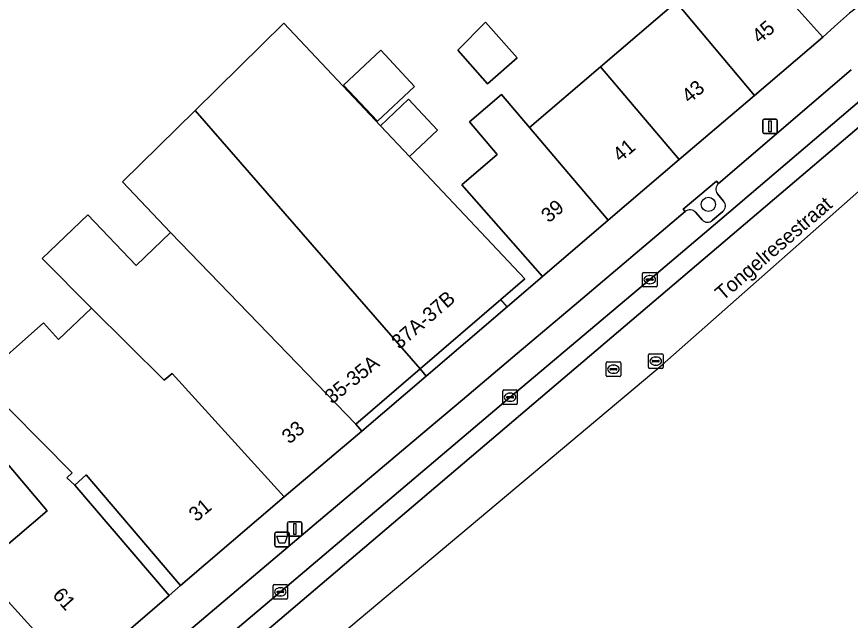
# Model space of a CAD drawing. Extents: x 161772 to 163126, y 383092 to 383917.
# Drawn here: x 162327.9 to 162385.3, y 383254.5 to 383296 of the extents above; entities that cross this region are included whole.
import ezdxf

# ---------------------------------------------------------------- set-up
doc = ezdxf.new("R2010")
doc.units = 0
for name, color, linetype in [('IMGEO_Afvalbak', 7, 'Continuous'), ('IMGEO_Boom', 7, 'Continuous'), ('IMGEO_Erf', 7, 'Continuous'), ('IMGEO_Kolk', 7, 'Continuous'), ('IMGEO_Lichtmast', 7, 'Continuous'), ('IMGEO_Openbare_ruimte_label', 7, 'Continuous'), ('IMGEO_Pand', 7, 'Continuous'), ('IMGEO_Pand_nummerreeks', 7, 'Continuous'), ('IMGEO_Pand_overbouw', 7, 'Continuous'), ('IMGEO_Parkeervlak_open', 7, 'Continuous'), ('IMGEO_Rijbaan_lokaal_gesloten', 7, 'Continuous'), ('IMGEO_Rioolput', 7, 'Continuous'), ('IMGEO_Verkeerseiland_groen', 7, 'Continuous'), ('IMGEO_Voetpad_open', 7, 'Continuous')]:
    doc.layers.add(name, color=color, linetype=linetype)

msp = doc.modelspace()

# ---------------------------------------------------------------- linework, layer by layer
at = {"layer": 'IMGEO_Afvalbak'}
for p, q in [((162345.628, 383259.67), (162345.628, 383260.47)), ((162345.628, 383260.47), (162345.628, 383259.67)), ((162345.728, 383260.57), (162346.518, 383260.57)), ((162346.518, 383260.57), (162345.728, 383260.57)), ((162346.618, 383260.47), (162346.618, 383259.67)), ((162346.618, 383259.67), (162346.618, 383260.47)), ((162346.518, 383259.57), (162345.728, 383259.57)), ((162345.728, 383259.57), (162346.518, 383259.57))]:
    msp.add_line(p, q, dxfattribs=at)
msp.add_lwpolyline([(162345.771, 383260.284), (162346.475, 383260.284), (162346.326, 383259.814), (162345.92, 383259.814), (162345.771, 383260.284)], dxfattribs=at)
for centre, start, end in [((162345.728, 383260.47), 90, 180), ((162345.728, 383260.47), 90, 180), ((162346.518, 383260.47), 0, 90), ((162346.518, 383260.47), 360, 90), ((162345.728, 383259.67), 180, 270), ((162345.728, 383259.67), 180, 270), ((162346.518, 383259.67), 270, 0), ((162346.518, 383259.67), 270, 0)]:
    msp.add_arc(centre, 0.1, start, end, dxfattribs=at)
at = {"layer": 'IMGEO_Boom'}
msp.add_circle((162375.479, 383283.12), 0.489, dxfattribs=at)
at = {"layer": 'IMGEO_Erf'}
for points in [[(162377.774, 383300.852), (162383.362, 383294.638), (162384.171, 383295.362), (162385.195, 383296.277)], [(162325.303, 383271.069), (162329.696, 383274.966), (162330.731, 383273.836), (162333.008, 383275.992), (162329.606, 383279.399), (162332.752, 383282.403), (162336.074, 383278.924), (162338.449, 383281.193), (162335.133, 383284.665), (162340.14, 383289.589), (162346.252, 383295.599), (162352.904, 383288.537), (162354.836, 383290.356), (162356.833, 383288.236), (162354.902, 383286.416), (162362.835, 383277.994), (162361.192, 383276.582), (162355.625, 383271.799), (162351.204, 383268.001), (162351.614, 383267.518), (162356.051, 383271.309), (162361.628, 383276.075), (162364.049, 383278.168), (162358.51, 383284.477), (162360.945, 383286.547), (162359.025, 383288.805), (162361.232, 383290.681), (162363.152, 383288.422), (162368.044, 383292.581), (162373.272, 383297.025)], [(162325.846, 383258.547), (162329.957, 383262.04), (162323.454, 383269.69)]]:
    msp.add_lwpolyline(points, dxfattribs=at)
for points in [[(162358.231, 383293.732), (162360.141, 383295.667), (162362.304, 383293.2), (162360.264, 383291.413)], [(162352.919, 383293.723), (162355.254, 383291.24), (162352.708, 383288.839), (162350.364, 383291.33)], [(162331.866, 383263.812), (162338.354, 383256.203), (162339.126, 383256.895), (162332.636, 383264.517)]]:
    msp.add_lwpolyline(points, close=True, dxfattribs=at)
at = {"layer": 'IMGEO_Kolk'}
for p, q in [((162371.021, 383278.445), (162371.873, 383278.445)), ((162370.946, 383277.519), (162370.946, 383278.371)), ((162371.205, 383277.939), (162371.205, 383277.951)), ((162371.643, 383277.902), (162371.245, 383277.902)), ((162371.248, 383277.988), (162371.646, 383277.988)), ((162371.434, 383278.225), (162371.459, 383278.225)), ((162371.689, 383277.951), (162371.689, 383277.939)), ((162371.947, 383278.371), (162371.947, 383277.519)), ((162371.873, 383277.445), (162371.021, 383277.445)), ((162371.457, 383277.665), (162371.432, 383277.665)), ((162361.324, 383269.426), (162361.324, 383270.278)), ((162361.399, 383270.352), (162362.251, 383270.352)), ((162361.583, 383269.846), (162361.583, 383269.858)), ((162362.021, 383269.809), (162361.623, 383269.809)), ((162361.626, 383269.895), (162362.024, 383269.895)), ((162361.812, 383270.132), (162361.837, 383270.132)), ((162362.067, 383269.858), (162362.067, 383269.846)), ((162362.325, 383270.278), (162362.325, 383269.426)), ((162362.251, 383269.352), (162361.399, 383269.352)), ((162361.835, 383269.572), (162361.81, 383269.572)), ((162345.508, 383256.032), (162345.508, 383256.884)), ((162345.583, 383256.958), (162346.435, 383256.958)), ((162345.996, 383256.738), (162346.021, 383256.738)), ((162346.509, 383256.884), (162346.509, 383256.032)), ((162345.767, 383256.452), (162345.767, 383256.464)), ((162346.205, 383256.415), (162345.807, 383256.415)), ((162345.81, 383256.501), (162346.208, 383256.501)), ((162346.019, 383256.178), (162345.994, 383256.178)), ((162346.251, 383256.464), (162346.251, 383256.452)), ((162346.435, 383255.958), (162345.583, 383255.958))]:
    msp.add_line(p, q, dxfattribs=at)
for points in [[(162371.021, 383278.445), (162371.873, 383278.445)], [(162370.946, 383277.519), (162370.946, 383278.371)], [(162371.947, 383278.371), (162371.947, 383277.519)], [(162371.873, 383277.445), (162371.021, 383277.445)], [(162361.324, 383269.426), (162361.324, 383270.278)], [(162361.399, 383270.352), (162362.251, 383270.352)], [(162362.325, 383270.278), (162362.325, 383269.426)], [(162362.251, 383269.352), (162361.399, 383269.352)], [(162345.508, 383256.032), (162345.508, 383256.884)], [(162345.583, 383256.958), (162346.435, 383256.958)], [(162346.509, 383256.884), (162346.509, 383256.032)], [(162346.435, 383255.958), (162345.583, 383255.958)]]:
    msp.add_lwpolyline(points, dxfattribs=at)
for centre, radius, start, end in [((162371.023, 383278.369), 0.0765, 91.55205, 178.44795), ((162371.023, 383278.369), 0.0765, 91.55205, 178.44795), ((162371.871, 383278.369), 0.0765, 1.55205, 88.44795), ((162371.871, 383278.369), 0.0765, 1.55205, 88.44795), ((162371.245, 383277.948), 0.0403, 85.87752, 175.75265), ((162371.242, 383277.938), 0.0366, 178.93798, 274.71019), ((162371.646, 383277.945), 0.043, 264.86636, 352.45326), ((162371.65, 383277.95), 0.0386, 1.73085, 96.63898), ((162371.023, 383277.521), 0.0765, 181.55205, 268.44795), ((162371.023, 383277.521), 0.0765, 181.55205, 268.44795), ((162371.871, 383277.521), 0.0765, 271.55205, 358.44795), ((162371.871, 383277.521), 0.0765, 271.55205, 358.44795), ((162361.401, 383270.276), 0.0765, 91.55205, 178.44795), ((162361.401, 383270.276), 0.0765, 91.55205, 178.44795), ((162361.623, 383269.855), 0.0403, 85.87752, 175.75265), ((162361.62, 383269.845), 0.0366, 178.93798, 274.71019), ((162362.024, 383269.852), 0.043, 264.86636, 352.45326), ((162362.028, 383269.857), 0.0386, 1.73085, 96.63898), ((162362.249, 383270.276), 0.0765, 1.55205, 88.44795), ((162362.249, 383270.276), 0.0765, 1.55205, 88.44795), ((162361.401, 383269.428), 0.0765, 181.55205, 268.44795), ((162361.401, 383269.428), 0.0765, 181.55205, 268.44795), ((162362.249, 383269.428), 0.0765, 271.55205, 358.44795), ((162362.249, 383269.428), 0.0765, 271.55205, 358.44795), ((162345.585, 383256.882), 0.0765, 91.55205, 178.44795), ((162345.585, 383256.882), 0.0765, 91.55205, 178.44795), ((162346.433, 383256.882), 0.0765, 1.55205, 88.44795), ((162346.433, 383256.882), 0.0765, 1.55205, 88.44795), ((162345.585, 383256.034), 0.0765, 181.55205, 268.44795), ((162345.585, 383256.034), 0.0765, 181.55205, 268.44795), ((162345.807, 383256.461), 0.0403, 85.87752, 175.75265), ((162345.804, 383256.451), 0.0366, 178.93798, 274.71019), ((162346.208, 383256.458), 0.043, 264.86636, 352.45326), ((162346.212, 383256.463), 0.0386, 1.73085, 96.63898), ((162346.433, 383256.034), 0.0765, 271.55205, 358.44795), ((162346.433, 383256.034), 0.0765, 271.55205, 358.44795)]:
    msp.add_arc(centre, radius, start, end, dxfattribs=at)
for centre, major_axis, ratio, start_param, end_param in [((162371.433, 383277.945), (-0.387, 0.002), 0.722429, 4.712389, 7.853982), ((162371.458, 383277.945), (-0.39, 0.002), 0.717154, 1.570796, 4.712389), ((162361.811, 383269.852), (-0.387, 0.002), 0.722429, 4.712389, 7.853982), ((162361.836, 383269.852), (-0.39, 0.002), 0.717154, 1.570796, 4.712389), ((162345.995, 383256.458), (-0.387, 0.002), 0.722429, 4.712389, 7.853982), ((162346.02, 383256.458), (-0.39, 0.002), 0.717154, 1.570796, 4.712389)]:
    msp.add_ellipse(centre, major_axis=major_axis, ratio=ratio, start_param=start_param, end_param=end_param, dxfattribs=at)
at = {"layer": 'IMGEO_Lichtmast'}
for p, q in [((162379.228, 383288.088), (162379.228, 383288.888)), ((162379.228, 383288.888), (162379.228, 383288.088)), ((162379.328, 383288.988), (162380.118, 383288.988)), ((162380.118, 383288.988), (162379.328, 383288.988)), ((162380.218, 383288.888), (162380.218, 383288.088)), ((162380.218, 383288.088), (162380.218, 383288.888)), ((162380.118, 383287.988), (162379.328, 383287.988)), ((162379.328, 383287.988), (162380.118, 383287.988)), ((162346.506, 383260.39), (162346.506, 383261.19)), ((162346.506, 383261.19), (162346.506, 383260.39)), ((162346.606, 383261.29), (162347.396, 383261.29)), ((162347.396, 383261.29), (162346.606, 383261.29)), ((162347.496, 383261.19), (162347.496, 383260.39)), ((162347.496, 383260.39), (162347.496, 383261.19)), ((162347.396, 383260.29), (162346.606, 383260.29)), ((162346.606, 383260.29), (162347.396, 383260.29))]:
    msp.add_line(p, q, dxfattribs=at)
for points in [[(162379.648, 383288.863), (162379.798, 383288.863), (162379.798, 383288.113), (162379.648, 383288.113), (162379.648, 383288.863)], [(162346.926, 383261.165), (162347.076, 383261.165), (162347.076, 383260.415), (162346.926, 383260.415), (162346.926, 383261.165)]]:
    msp.add_lwpolyline(points, dxfattribs=at)
for centre, start, end in [((162379.328, 383288.888), 90, 180), ((162379.328, 383288.888), 90, 180), ((162380.118, 383288.888), 0, 90), ((162380.118, 383288.888), 360, 90), ((162379.328, 383288.088), 180, 270), ((162379.328, 383288.088), 180, 270), ((162380.118, 383288.088), 270, 0), ((162380.118, 383288.088), 270, 0), ((162346.606, 383261.19), 90, 180), ((162346.606, 383261.19), 90, 180), ((162347.396, 383261.19), 0, 90), ((162347.396, 383261.19), 360, 90), ((162346.606, 383260.39), 180, 270), ((162346.606, 383260.39), 180, 270), ((162347.396, 383260.39), 270, 0), ((162347.396, 383260.39), 270, 0)]:
    msp.add_arc(centre, 0.1, start, end, dxfattribs=at)
at = {"layer": 'IMGEO_Pand'}
for points in [[(162378.645, 383290.616), (162383.362, 383294.638), (162377.774, 383300.852), (162373.965, 383297.614), (162373.272, 383297.025)], [(162373.468, 383286.2), (162378.645, 383290.616), (162373.272, 383297.025), (162368.044, 383292.581)], [(162360.264, 383291.413), (162362.304, 383293.2), (162360.141, 383295.667), (162358.231, 383293.732)], [(162354.902, 383286.416), (162352.904, 383288.537), (162346.252, 383295.599), (162340.14, 383289.589), (162355.625, 383271.799), (162361.192, 383276.582), (162362.835, 383277.994)], [(162352.708, 383288.839), (162355.254, 383291.24), (162352.919, 383293.723), (162350.364, 383291.33)], [(162373.468, 383286.2), (162368.044, 383292.581), (162363.152, 383288.422), (162368.582, 383282.034)], [(162363.152, 383288.422), (162361.232, 383290.681), (162359.025, 383288.805), (162360.945, 383286.547), (162358.51, 383284.477), (162364.049, 383278.168), (162368.582, 383282.034)], [(162352.904, 383288.537), (162354.902, 383286.416), (162356.833, 383288.236), (162354.836, 383290.356)], [(162340.14, 383289.589), (162335.133, 383284.665), (162338.449, 383281.193), (162351.204, 383268.001), (162355.625, 383271.799)], [(162333.008, 383275.992), (162338.004, 383271.019), (162338.57, 383271.481), (162346.265, 383262.997), (162351.614, 383267.518), (162351.204, 383268.001), (162338.449, 383281.193), (162336.074, 383278.924), (162332.752, 383282.403), (162329.606, 383279.399)], [(162333.008, 383275.992), (162330.731, 383273.836), (162329.696, 383274.966), (162325.303, 383271.069), (162331.67, 383264.649), (162331.304, 383264.297), (162331.866, 383263.812), (162332.636, 383264.517), (162339.126, 383256.895), (162346.265, 383262.997), (162338.57, 383271.481), (162338.004, 383271.019)], [(162325.949, 383257.238), (162331.007, 383251.661), (162331.911, 383250.664), (162338.354, 383256.203), (162331.866, 383263.812), (162331.304, 383264.297), (162331.67, 383264.649), (162325.303, 383271.069), (162325.199, 383271.174), (162323.454, 383269.69), (162329.957, 383262.04), (162325.846, 383258.547), (162326.5, 383257.928)]]:
    msp.add_lwpolyline(points, close=True, dxfattribs=at)
at = {"layer": 'IMGEO_Pand_overbouw'}
for points in [[(162355.625, 383271.799), (162356.051, 383271.309), (162361.628, 383276.075), (162361.192, 383276.582)], [(162351.204, 383268.001), (162351.614, 383267.518), (162356.051, 383271.309), (162355.625, 383271.799)]]:
    msp.add_lwpolyline(points, close=True, dxfattribs=at)
at = {"layer": 'IMGEO_Parkeervlak_open'}
for points in [[(162333.755, 383246.101), (162336.091, 383248.087), (162338.371, 383250), (162339.489, 383250.937), (162346.009, 383256.458), (162358.661, 383267.166), (162361.825, 383269.852), (162371.447, 383277.945), (162376.27, 383282.045), (162386.657, 383290.883), (162388.29, 383292.272), (162389.114, 383292.973)], [(162385.31, 383292.38), (162376.165, 383284.56)], [(162376.097, 383283.851), (162376.53, 383283.334)], [(162373.871, 383282.628), (162366.246, 383276.167), (162362.316, 383272.868), (162358.541, 383269.679), (162356.259, 383267.741), (162348.336, 383261.062), (162338.185, 383252.49), (162335.261, 383250), (162334.814, 383249.62)], [(162375.054, 383282.065), (162374.613, 383282.571)], [(162376.471, 383282.639), (162375.757, 383282.028)]]:
    msp.add_lwpolyline(points, dxfattribs=at)
for centre, radius, start, end in [((162376.554, 383284.165), 0.554, 134.5259, 214.51717), ((162376.168, 383283.015), 0.483, 308.87244, 41.42291), ((162374.212, 383282.214), 0.537, 41.72156, 129.49284), ((162375.422, 383282.357), 0.47, 218.44139, 315.53304)]:
    msp.add_arc(centre, radius, start, end, dxfattribs=at)
at = {"layer": 'IMGEO_Rijbaan_lokaal_gesloten'}
for points in [[(162174.82, 383097.237), (162181.627, 383109.075), (162185.082, 383115.085), (162267.807, 383184.457), (162331.864, 383238.174), (162334.992, 383240.797), (162372.302, 383272.085), (162439.186, 383331.12), (162452.553, 383342.284), (162503.092, 383384.494), (162503.092, 383384.494), (162502.922, 383384.713), (162501.18, 383386.596), (162499.827, 383385.459), (162477.128, 383365.985), (162459.036, 383350.651), (162175.227, 383109.464), (162171.607, 383105.25), (162169.364, 383100.909), (162168.706, 383099.067), (162168.602, 383098.586), (162174.82, 383097.237), (162174.82, 383097.237)], [(162167.684, 383101.555), (162167.287, 383100.424), (162167.052, 383099.838), (162166.946, 383099.458), (162166.911, 383099.334), (162166.809, 383098.975), (162168.602, 383098.586), (162168.706, 383099.067), (162169.364, 383100.909), (162171.607, 383105.25), (162175.227, 383109.464), (162459.036, 383350.651)], [(162424.727, 383323.567), (162416.702, 383316.671), (162405.717, 383307.214), (162401.779, 383303.906), (162398.39, 383300.913), (162389.114, 383292.973), (162388.29, 383292.272), (162386.657, 383290.883), (162376.27, 383282.045), (162371.447, 383277.945), (162361.825, 383269.852), (162358.661, 383267.166), (162346.009, 383256.458), (162339.489, 383250.937), (162338.371, 383250), (162336.091, 383248.087), (162333.755, 383246.101), (162333.493, 383245.878), (162332.127, 383244.723), (162325.904, 383239.465)]]:
    msp.add_lwpolyline(points, dxfattribs=at)
at = {"layer": 'IMGEO_Rioolput'}
for p, q in [((162371.355, 383271.913), (162371.355, 383272.765)), ((162371.43, 383272.839), (162372.282, 383272.839)), ((162372.356, 383272.765), (162372.356, 383271.913)), ((162368.444, 383271.353), (162368.444, 383272.205)), ((162368.519, 383272.279), (162369.371, 383272.279)), ((162369.445, 383272.205), (162369.445, 383271.353)), ((162371.614, 383272.333), (162371.614, 383272.345)), ((162372.052, 383272.296), (162371.654, 383272.296)), ((162371.657, 383272.382), (162372.055, 383272.382)), ((162371.843, 383272.619), (162371.868, 383272.619)), ((162372.098, 383272.345), (162372.098, 383272.333)), ((162368.703, 383271.773), (162368.703, 383271.785)), ((162369.141, 383271.736), (162368.743, 383271.736)), ((162368.746, 383271.822), (162369.144, 383271.822)), ((162368.932, 383272.059), (162368.957, 383272.059)), ((162369.187, 383271.785), (162369.187, 383271.773)), ((162372.282, 383271.839), (162371.43, 383271.839)), ((162371.866, 383272.059), (162371.841, 383272.059)), ((162369.371, 383271.279), (162368.519, 383271.279)), ((162368.955, 383271.499), (162368.93, 383271.499))]:
    msp.add_line(p, q, dxfattribs=at)
for points in [[(162371.355, 383271.913), (162371.355, 383272.765)], [(162371.43, 383272.839), (162372.282, 383272.839)], [(162372.356, 383272.765), (162372.356, 383271.913)], [(162368.444, 383271.353), (162368.444, 383272.205)], [(162368.519, 383272.279), (162369.371, 383272.279)], [(162369.445, 383272.205), (162369.445, 383271.353)], [(162372.282, 383271.839), (162371.43, 383271.839)], [(162369.371, 383271.279), (162368.519, 383271.279)]]:
    msp.add_lwpolyline(points, dxfattribs=at)
for centre, radius, start, end in [((162371.432, 383272.763), 0.0765, 91.55205, 178.44795), ((162371.432, 383272.763), 0.0765, 91.55205, 178.44795), ((162372.28, 383272.763), 0.0765, 1.55205, 88.44795), ((162372.28, 383272.763), 0.0765, 1.55205, 88.44795), ((162368.521, 383272.203), 0.0765, 91.55205, 178.44795), ((162368.521, 383272.203), 0.0765, 91.55205, 178.44795), ((162369.369, 383272.203), 0.0765, 1.55205, 88.44795), ((162369.369, 383272.203), 0.0765, 1.55205, 88.44795), ((162371.654, 383272.342), 0.0403, 85.87752, 175.75265), ((162371.651, 383272.332), 0.0366, 178.93798, 274.71019), ((162372.055, 383272.339), 0.043, 264.86636, 352.45326), ((162372.059, 383272.344), 0.0386, 1.73085, 96.63898), ((162368.743, 383271.782), 0.0403, 85.87752, 175.75265), ((162368.74, 383271.772), 0.0366, 178.93798, 274.71019), ((162369.144, 383271.779), 0.043, 264.86636, 352.45326), ((162369.148, 383271.784), 0.0386, 1.73085, 96.63898), ((162371.432, 383271.915), 0.0765, 181.55205, 268.44795), ((162371.432, 383271.915), 0.0765, 181.55205, 268.44795), ((162372.28, 383271.915), 0.0765, 271.55205, 358.44795), ((162372.28, 383271.915), 0.0765, 271.55205, 358.44795), ((162368.521, 383271.355), 0.0765, 181.55205, 268.44795), ((162368.521, 383271.355), 0.0765, 181.55205, 268.44795), ((162369.369, 383271.355), 0.0765, 271.55205, 358.44795), ((162369.369, 383271.355), 0.0765, 271.55205, 358.44795)]:
    msp.add_arc(centre, radius, start, end, dxfattribs=at)
for centre, major_axis, ratio, start_param, end_param in [((162371.842, 383272.339), (-0.387, 0.002), 0.722429, 4.712389, 7.853982), ((162371.867, 383272.339), (-0.39, 0.002), 0.717154, 1.570796, 4.712389), ((162368.931, 383271.779), (-0.387, 0.002), 0.722429, 4.712389, 7.853982), ((162368.956, 383271.779), (-0.39, 0.002), 0.717154, 1.570796, 4.712389)]:
    msp.add_ellipse(centre, major_axis=major_axis, ratio=ratio, start_param=start_param, end_param=end_param, dxfattribs=at)
at = {"layer": 'IMGEO_Verkeerseiland_groen'}
for points in [[(162376.165, 383284.56), (162376.031, 383284.73), (162373.738, 383282.782), (162373.871, 383282.628)], [(162376.53, 383283.334), (162376.097, 383283.851)], [(162374.613, 383282.571), (162375.054, 383282.065)], [(162375.757, 383282.028), (162376.471, 383282.639)]]:
    msp.add_lwpolyline(points, dxfattribs=at)
for centre, radius, start, end in [((162376.554, 383284.165), 0.554, 134.5259, 214.51717), ((162376.168, 383283.015), 0.483, 308.87244, 41.42291), ((162374.212, 383282.214), 0.537, 41.72156, 129.49284), ((162375.422, 383282.357), 0.47, 218.44139, 315.53304)]:
    msp.add_arc(centre, radius, start, end, dxfattribs=at)
at = {"layer": 'IMGEO_Voetpad_open'}
for points in [[(162387.917, 383298.355), (162385.195, 383296.277), (162384.171, 383295.362), (162383.362, 383294.638), (162378.645, 383290.616), (162373.468, 383286.2), (162368.582, 383282.034), (162364.049, 383278.168), (162361.628, 383276.075), (162356.051, 383271.309), (162351.614, 383267.518), (162346.265, 383262.997), (162339.126, 383256.895), (162338.354, 383256.203), (162331.911, 383250.664), (162330.334, 383249.303), (162330.077, 383249.586), (162323.973, 383244.46)], [(162334.814, 383249.62), (162335.261, 383250), (162338.185, 383252.49), (162348.336, 383261.062), (162356.259, 383267.741), (162358.541, 383269.679), (162362.316, 383272.868), (162366.246, 383276.167), (162373.871, 383282.628), (162373.738, 383282.782), (162376.031, 383284.73), (162376.165, 383284.56), (162385.31, 383292.38)]]:
    msp.add_lwpolyline(points, dxfattribs=at)
msp.add_lwpolyline([(162325.949, 383257.238), (162324.476, 383255.781), (162330.077, 383249.586), (162330.334, 383249.303), (162331.911, 383250.664), (162331.007, 383251.661)], close=True, dxfattribs=at)

# ---------------------------------------------------------------- texts
at = {"layer": 'IMGEO_Openbare_ruimte_label'}
msp.add_text('Tongelresestraat', height=1, rotation=40.61994, dxfattribs=at).set_placement((162376.476, 383276.45))
at = {"layer": 'IMGEO_Pand_nummerreeks'}
for s, rotation, p in [('45', 40.3654, (162379.006, 383294.142)), ('43', 40.3654, (162374.169, 383290.03)), ('41', 40.3654, (162369.417, 383285.991)), ('39', 40.36488, (162364.494, 383281.806)), ('37A-37B', 40.88627, (162354.199, 383273.102)), ('35-35A', 38.92754, (162349.564, 383269.341)), ('33', 40.36422, (162346.635, 383266.588)), ('31', 40.14543, (162340.229, 383261.235)), ('61', 311.89722, (162330.264, 383256.204))]:
    msp.add_text(s, height=1, rotation=rotation, dxfattribs=at).set_placement(p)

doc.saveas('drawing.dxf')
